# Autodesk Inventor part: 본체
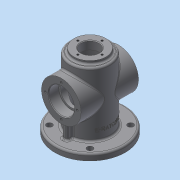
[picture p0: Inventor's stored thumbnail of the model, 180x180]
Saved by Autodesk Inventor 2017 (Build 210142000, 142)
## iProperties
Created: 2020-05
Part Number: 본체
Material: 알루미늄 6061
Document SubType Name: Modeling
Designer: mduedu
Density: 2.71 g/cm^3
Mass: 777.292 g
Surface Area: 687.933 cm^2
Volume: 286.824 cm^3
Appearance: 기본값
Author: mduedu
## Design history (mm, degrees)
sketch "스케치1"
  geometry: C1 r 32 at (0, 0); 1 further point
  constraints: 1 centre point, 1 coincident
  dimensions: "d0" = 64 diameter of C1
extrude "돌출1" new body sketch "스케치1" distance "d1" = 110; taper "d2" = 0 deg
feature "쉘1" dims "d3" = 8
fillet "모깎기1" dims "d4" = 3
fillet "모깎기2" dims "d5" = 3
sketch "스케치2"
  geometry: C1 r 25 at (0, 0); 1 further point
  constraints: 1 centre point, 1 coincident
  dimensions: "d6" = 50 diameter of C1
extrude "돌출2" join sketch "스케치2" distance "d7" = 5; taper "d8" = 0 deg
sketch "스케치3"
  geometry: C1 r 14 at (0, 0); 1 further point
  constraints: 1 centre point, 1 coincident
  dimensions: "d9" = 28 diameter of C1
extrude "돌출3" cut sketch "스케치3" stored distance "d10" = 5; taper "d11" = 0 deg
fillet "모깎기3" dims "d12" = 3
sketch "스케치4"
  geometry: C1 r 32 at (0, 0) reference; C2 r 55 at (0, 0); 1 further point
  constraints: 1 centre point, 1 coincident
  dimensions: "d13" = 110 diameter of C2
extrude "돌출4" join sketch "스케치4" distance "d14" = 10; taper "d15" = 0 deg
sketch "스케치5"
  geometry: L1 (0, 0)-(-31.82, 31.82); L2 (0, 0)-(-45, 0); A1 r 45 centre (0, 0) between (-31.82, 31.82) and (-45, 0); 1 further point
  constraints: 4 end point, 2 point on circle, 1 centre point, 1 coincident, 1 horizontal
  dimensions: "d16" = 90 diameter of A1; "d71" = 45 deg angle of L1 L2
hole "구멍1" sketch "스케치5" at (-31.82, 31.82) diameter "d17" = 9; stored, may be unused: countersink angle "d21" = 90 deg, drill point angle "d23" = 118 deg; dims "d18" = 6, "d19" = 4, "d20" = 2, "d22" = 8
fillet "모깎기4" dims "d27" = 3
node "작업 평면1"
sketch "스케치6"
  geometry: L1 (0, 55)-(0, -55) reference; C1 r 31 at (-65, 0); 2 further points
  constraints: 1 centre point, 1 horizontal alignment, 1 midpoint
  dimensions: "d31" = 62 diameter of C1; "d32" = 65 distance from line of C1.centre L1
extrude "돌출5" join sketch "스케치6" stored distance "d33" = 10; taper "d34" = 0 deg
fillet "모깎기5" dims "d35" = 3
sketch "스케치7"
  geometry: C1 r 31 at (0, 0) reference; C2 r 20 at (0, 0); 1 further point
  constraints: 1 centre point, 1 coincident
  dimensions: "d36" = 40 diameter of C2
extrude "돌출6" cut sketch "스케치7" distance "d37" = 16; taper "d38" = 0 deg
sketch "스케치8"
  geometry: C1 r 20 at (0, 0) reference; C2 r 17 at (0, 0); 1 further point
  constraints: 1 centre point, 1 coincident
  dimensions: "d39" = 34 diameter of C2
extrude "돌출7" cut sketch "스케치8" stored distance "d40" = 15; taper "d41" = 0 deg
fillet "모깎기6" dims "d42" = 0.3
chamfer "모따기1" distance "d43" = 1; stored, may be unused: second distance "d44" = 2, angle "d45" = 45 deg
chamfer "모따기2" distance "d46" = 1; stored, may be unused: second distance "d47" = 2, angle "d48" = 45 deg
sketch "스케치9" dims "d49" = 50
  geometry: C1 r 31 at (0, 0) reference; 3 further points
  constraints: 2 vertical alignment, 1 coincident, 2 other
hole "구멍2" sketch "스케치9" at (0, 25) diameter "d50" = 3.242; stored, may be unused: countersink angle "d54" = 90 deg, drill point angle "d56" = 118 deg; dims "d51" = 7, "d52" = 4, "d53" = 2, "d55" = 9
sketch "스케치10" dims "d60" = 38
  geometry: 3 further points
  constraints: 2 vertical alignment, 1 coincident, 2 other
hole "구멍3" sketch "스케치10" at (0, 19) diameter "d61" = 3.242; stored, may be unused: countersink angle "d65" = 90 deg, drill point angle "d67" = 118 deg; dims "d62" = 8, "d63" = 4, "d64" = 2, "d66" = 10
sketch "스케치11"
  geometry: L1 (32, 31)-(32, 13) reference; L2 (35, 10)-(52, 10) reference; L3 (55, 7)-(55, 0) reference; L4 (55, 0)-(24, 0) reference; L5 (24, 0)-(24, 48) reference; L6 (24, 48)-(29, 48) reference; L7 (29, 48)-(29, 45.3) reference; L8 (29.3, 45)-(44, 45) reference; L9 (44, 45)-(45, 44) reference; L10 (45, 44)-(45, 41.621) reference; L11 (45, 41.621)-(36, 41.621) reference; L12 (36, 41.621)-(35.026, 40) reference; L13 (35.026, 40)-(36, 38.379) reference; L14 (36, 38.379)-(45, 38.379) reference; L15 (45, 38.379)-(45, 34) reference; L16 (45, 34)-(35, 34) reference; L17 (-32, 13)-(-32, 31) reference; L18 (-35, 34)-(-45, 34) reference; L19 (-45, 34)-(-45, 38.379) reference; L20 (-45, 38.379)-(-36, 38.379) reference; L21 (-36, 38.379)-(-35.026, 40) reference; L22 (-35.026, 40)-(-36, 41.621) reference; L23 (-36, 41.621)-(-45, 41.621) reference; L24 (-45, 41.621)-(-45, 44) reference; L25 (-45, 44)-(-44, 45) reference; L26 (-44, 45)-(-29.3, 45) reference; L27 (-29, 45.3)-(-29, 48) reference; L28 (-29, 48)-(-24, 48) reference; L29 (-24, 48)-(-24, 0) reference; L30 (-24, 0)-(-55, 0) reference; L31 (-55, 0)-(-55, 7) reference; L32 (-52, 10)-(-35, 10) reference; L33 (-25, 113)-(-25, 115) reference; L34 (-25, 115)-(-20.621, 115) reference; L35 (-20.621, 115)-(-20.621, 105) reference; L36 (-20.621, 105)-(-19, 104.026) reference; L37 (-19, 104.026)-(-17.379, 105) reference; L38 (-17.379, 105)-(-17.379, 115) reference; L39 (-17.379, 115)-(-15, 115) reference; L40 (-15, 115)-(-14, 114) reference; L41 (-14, 114)-(-14, 102) reference; L42 (-14, 102)-(-21, 102) reference; L43 (-24, 99)-(-24, 82) reference; L44 (-24, 82)-(-29, 82) reference; L45 (-29, 82)-(-29, 84.7) reference; L46 (-29.3, 85)-(-44, 85) reference; L47 (-44, 85)-(-45, 86) reference; L48 (-45, 86)-(-45, 88.379) reference; L49 (-45, 88.379)-(-36, 88.379) reference; L50 (-36, 88.379)-(-35.026, 90) reference; L51 (-35.026, 90)-(-36, 91.621) reference; L52 (-36, 91.621)-(-45, 91.621) reference; L53 (-45, 91.621)-(-45, 96) reference; L54 (-45, 96)-(-35, 96) reference; L55 (-32, 99)-(-32, 107) reference; L56 (-29, 110)-(-28, 110) reference; L57 (28, 110)-(29, 110) reference; L58 (32, 107)-(32, 99) reference; L59 (35, 96)-(45, 96) reference; L60 (45, 96)-(45, 91.621) reference; L61 (45, 91.621)-(36, 91.621) reference; L62 (36, 91.621)-(35.026, 90) reference; L63 (35.026, 90)-(36, 88.379) reference; L64 (36, 88.379)-(45, 88.379) reference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; A1 r 3 centre (35, 13) between (32, 13) and (35, 10) reference; A2 r 3 centre (52, 7) between (55, 7) and (52, 10) reference; A3 r 0.3 centre (29.3, 45.3) between (29, 45.3) and (29.3, 45) reference; A4 r 0.3 centre (-29.3, 45.3) between (-29.3, 45) and (-29, 45.3) reference; A5 r 3 centre (-52, 7) between (-52, 10) and (-55, 7) reference; A6 r 3 centre (-35, 13) between (-35, 10) and (-32, 13) reference; A7 r 3 centre (-28, 113) between (-28, 110) and (-25, 113) reference; A8 r 3 centre (-21, 99) between (-21, 102) and (-24, 99) reference; A9 r 0.3 centre (-29.3, 84.7) between (-29, 84.7) and (-29.3, 85) reference; A10 r 3 centre (-29, 107) between (-29, 110) and (-32, 107) reference; A11 r 3 centre (28, 113) between (25, 113) and (28, 110) reference; A12 r 3 centre (29, 107) between (32, 107) and (29, 110) reference; A13 r 0.3 centre (29.3, 84.7) between (29.3, 85) and (29, 84.7) reference; A14 r 3 centre (21, 99) between (24, 99) and (21, 102) reference; 1 further point
  constraints: 2 end point, 1 midpoint, 1 perpendicular, 1 point on line, 4 other
  dimensions: "d73" = 5 distance between parallel lines of L81 L19
feature "리브1" sketch "스케치11" dims "d74" = 1, "d75" = 8, "d76" = 0, "d77" = 0, "d78" = 1, "d79" = 1
fillet "모깎기7" dims "d80" = 3
fillet "모깎기8" dims "d81" = 3
node "작업 평면2"
sketch "스케치12"
  geometry: 2 further points
  constraints: 1 vertical alignment, 1 other
  dimensions: "d83" = 25 distance of point (0, 25) point (0, 0)
feature "엠보싱1" sketch "스케치12" dims "d0" = 64, "d84" = 0.5, "d85" = 0
node "솔리드1"
pattern_circular "원형 패턴1" dims angle "d25" = 360 deg
mirror "대칭1"
mirror "대칭2"
pattern_circular "원형 패턴2" dims angle "d58" = 360 deg
mirror "대칭3"
pattern_circular "원형 패턴3" dims angle "d69" = 360 deg
mirror "대칭4"
node "투영된 루프1"
node "투영된 루프2"
node "절단 모서리 투영1"
other parameters: "d30" = -45
